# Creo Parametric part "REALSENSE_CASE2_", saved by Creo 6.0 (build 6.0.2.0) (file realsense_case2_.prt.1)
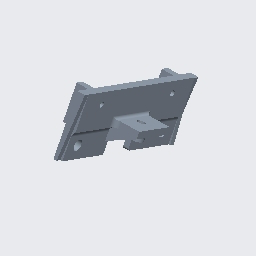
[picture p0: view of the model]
Units: Inch lbm Second (Pro/E Default); INCH, POUND, SECS

Created from: REALSENSE_CASE2.PRT

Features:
  1. datum plane "RIGHT"
  2. datum plane "TOP"
  3. datum plane "FRONT"
  4. coordinate system
  5. curve
  6. protrusion
  7. curve
  8. protrusion
  9. curve
  10. cut
  11. curve
  12. cut
  13. curve
  14. protrusion
  15. curve
  16. cut
  17. curve
  18. extrusion "Extrude 7"
  19. sketch "Sketch 8"
  20. extrusion "Extrude 8"
  21. sketch "Sketch 10"
  22. extruded cut "Extrude 10"
  23. sketch "Sketch 11"
  24. extruded cut "Extrude 11"
  25. sketch "Sketch 12"
  26. extruded cut "Extrude 12"
  27. sketch "Sketch 13"
  28. extrusion "Extrude 13"
  29. sketch "Sketch 14"
  30. extruded cut "Extrude 14"
  31. sketch "Sketch 19"
  32. extrusion "Extrude 19"
  33. round "Round 1"
  34. sketch "Sketch 15"
  35. extruded cut "Extrude 15"
  36. sketch "Sketch 16"
  37. extruded cut "Extrude 16"
  38. sketch "Sketch 17"
  39. extrusion "Extrude 17"
  40. sketch "Sketch 18"
  41. extrusion "Extrude 18"
  42. round "Round 2"

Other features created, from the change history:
  sketch "Sketch 9"
  extrusion "Extrude 9"
  sketch "Sketch 14"
  sketch "Sketch 15"
  sketch "Sketch 17"
  extrusion "Extrude 17"

Surfaces: 32 plane, 17 cylinder, 2 torus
